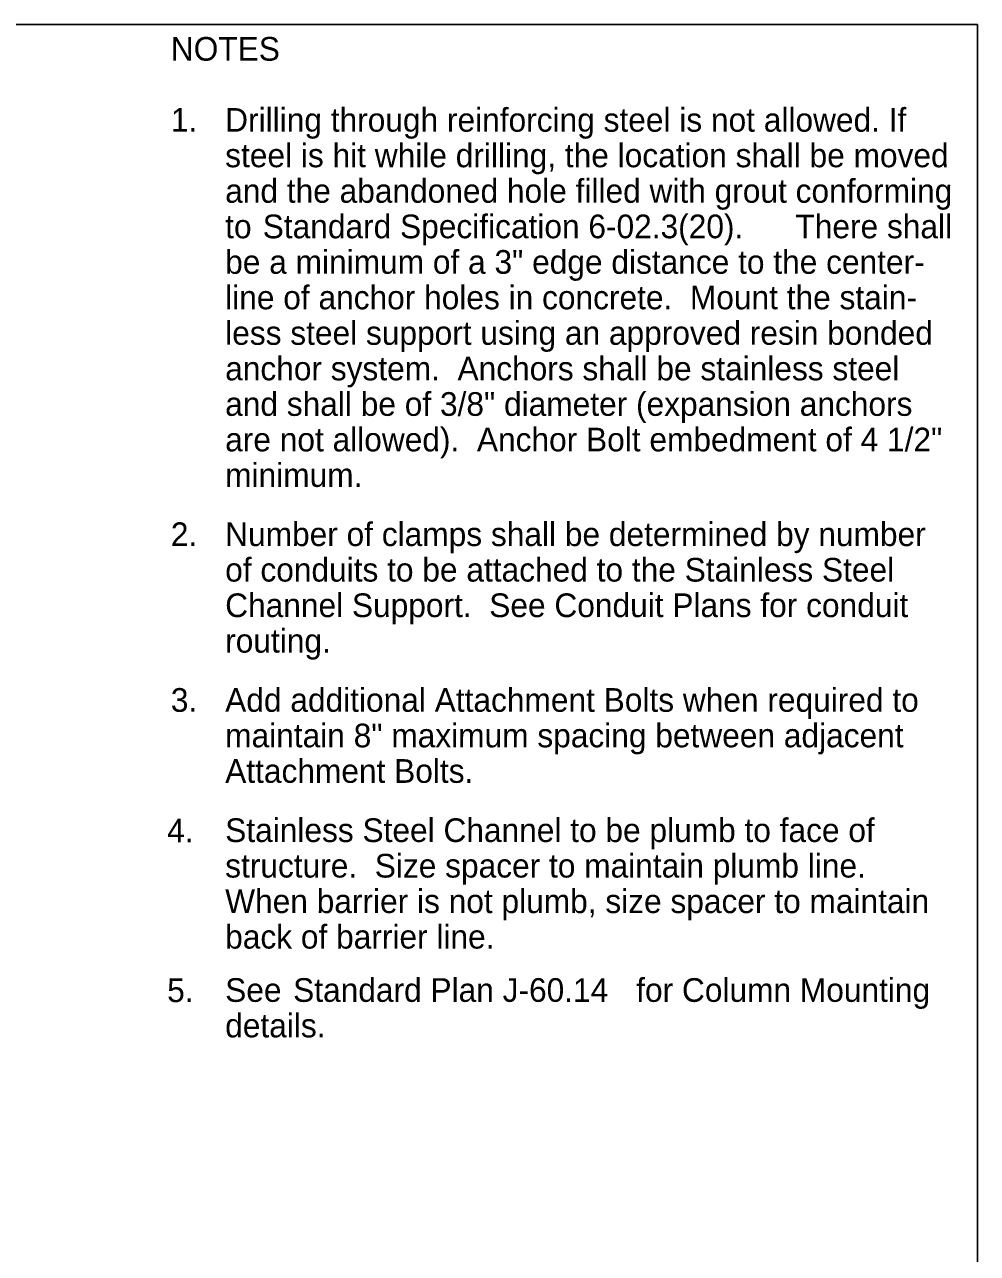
# Model space of a CAD drawing. Extents: x 99862 to 103151, y 100000 to 102076.
# Drawn here: x 102346 to 103151, y 101038 to 102076 of the extents above; entities that cross this region are included whole.
import ezdxf

# ---------------------------------------------------------------- set-up
doc = ezdxf.new("R2010")
doc.units = 0
for name, color, linetype in [('Level 1', 7, 'Continuous'), ('Level 20', 7, 'Continuous'), ('Level 60', 7, 'Continuous')]:
    doc.layers.add(name, color=color, linetype=linetype)

msp = doc.modelspace()

# ---------------------------------------------------------------- linework, layer by layer
at = {"layer": 'Level 1'}
msp.add_lwpolyline([(99862, 99999.5), (103151, 99999.5), (103151, 102075.5), (99862, 102075.5)], close=True, dxfattribs=at)
at = {"layer": 'Level 60'}
msp.add_line((103151, 102075.5), (103151, 102075.5), dxfattribs=at)

# ---------------------------------------------------------------- texts
at = {"layer": 'Level 20'}
for s, p in [('NOTES', (102469.8, 102045)), ('1.', (102469.8, 101985)), ('Drilling through reinforcing steel is not allowed. If ', (102515.7, 101985)), ('steel is hit while drilling, the location shall be moved ', (102515.7, 101955)), ('and the abandoned hole filled with grout conforming ', (102515.7, 101925)), ('to ', (102515.7, 101895)), ('Standard Specification 6-02.3(20).  ', (102547.4, 101895)), ('There shall ', (102997.3, 101895)), ('be a minimum of a 3" edge distance to the center-', (102515.7, 101865)), ('line of anchor holes in concrete.  Mount the stain-', (102515.7, 101835)), ('less steel support using an approved resin bonded ', (102515.7, 101805)), ('anchor system.  Anchors shall be stainless steel ', (102515.7, 101775)), ('and shall be of 3/8" diameter (expansion anchors ', (102515.7, 101745)), ('are not allowed).  Anchor Bolt embedment of 4 1/2" ', (102515.7, 101715)), ('minimum.', (102515.7, 101685)), ('2.', (102469.8, 101635)), ('Number of clamps shall be determined by number ', (102515.7, 101635)), ('of conduits to be attached to the Stainless Steel ', (102515.7, 101605)), ('Channel Support.  See Conduit Plans for conduit ', (102515.7, 101575)), ('routing.', (102515.7, 101545)), ('3.', (102469.8, 101495)), ('Add additional Attachment Bolts when required to ', (102515.7, 101495)), ('maintain 8" maximum spacing between adjacent ', (102515.7, 101465)), ('Attachment Bolts.', (102515.7, 101435)), ('4.', (102466.7, 101384.8)), ('Stainless Steel Channel to be plumb to face of', (102515.7, 101385)), ('structure.  Size spacer to maintain plumb line.', (102515.7, 101355)), ('When barrier is not plumb, size spacer to maintain', (102515.7, 101325)), ('back of barrier line.', (102515.7, 101295)), ('5.', (102466.7, 101249.8)), ('See ', (102515.7, 101250)), ('Standard Plan J-60.14', (102573.1, 101250)), (' for Column Mounting', (102855.4, 101250)), ('details.', (102515.7, 101220))]:
    msp.add_text(s, height=20, dxfattribs=at).set_placement(p)

doc.saveas('drawing.dxf')
